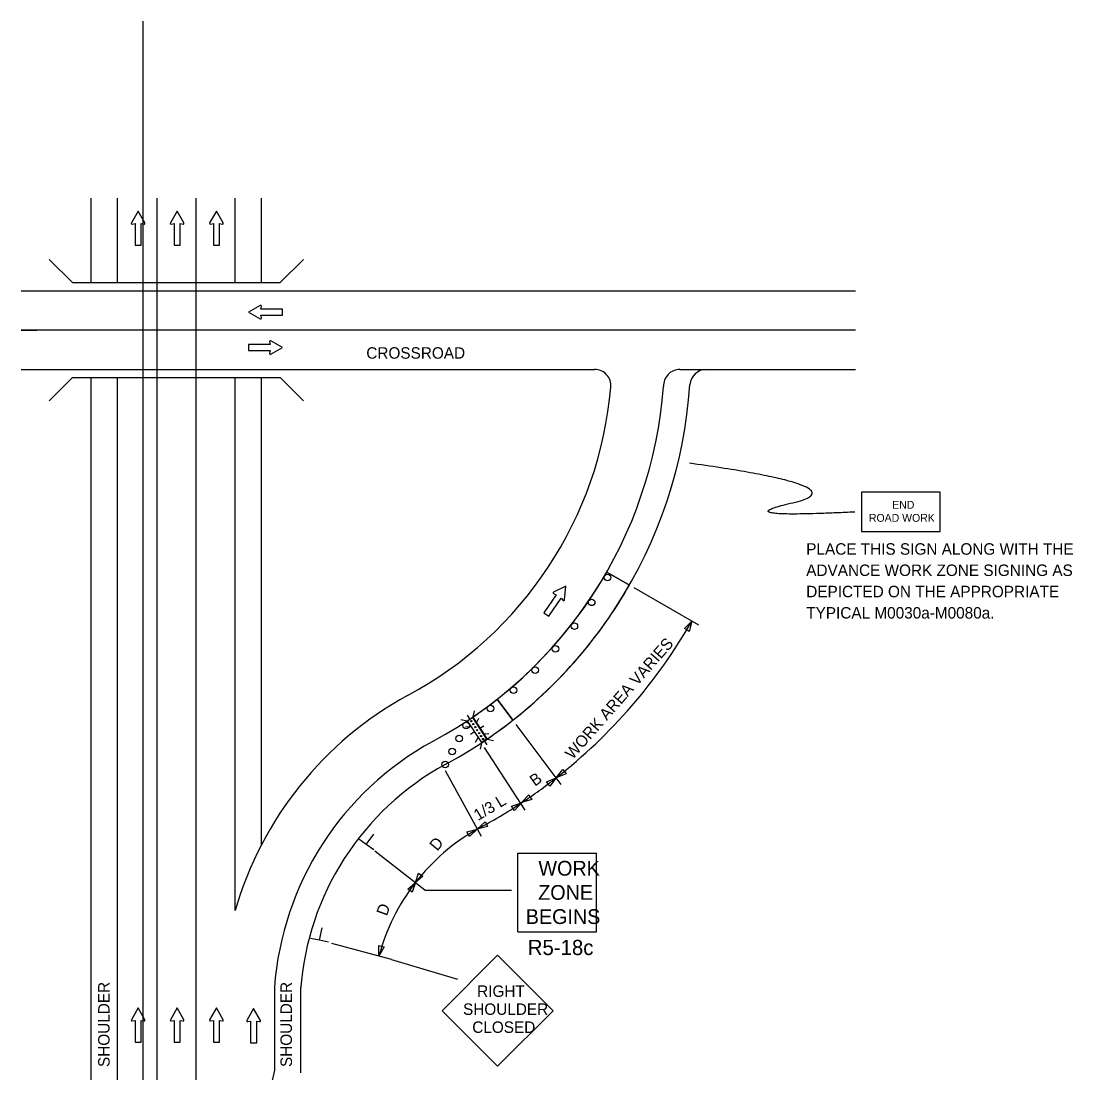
# Model space of a CAD drawing. Extents: x 16739 to 18471, y 6430 to 8295.
# Drawn here: x 16739 to 17381, y 7653 to 8295 of the extents above; entities that cross this region are included whole.
import ezdxf

# ---------------------------------------------------------------- set-up
doc = ezdxf.new("R2010")
doc.units = 0
for name, color, linetype in [('ALI_LEGAL_EX', 7, 'Continuous'), ('MT_SCRATCH_LEVEL_A', 7, 'Continuous'), ('MT_SCRATCH_LEVEL_E', 7, 'Continuous'), ('PAVT_EDGE_EX', 7, 'Continuous'), ('TRAFFIC_SIGNS_PR', 7, 'Continuous'), ('TYPICAL_TEXT_DIMEN_PR', 7, 'Continuous')]:
    doc.layers.add(name, color=color, linetype=linetype)

msp = doc.modelspace()

# ---------------------------------------------------------------- linework, layer by layer
at = {"layer": 'ALI_LEGAL_EX'}
for p, q in [((16813.1, 7643.13), (16813.1, 8295.46)), ((16821.4, 8187.24), (16821.4, 7232.8)), ((16845.4, 8187.24), (16845.4, 7232.8)), ((17248.19, 8106.7), (16738.55, 8106.7)), ((16893.33, 7654.82), (16893.33, 7654.82))]:
    msp.add_line(p, q, dxfattribs=at)
for points in [[(16821.4, 8187.24), (16821.4, 8162.24)], [(16845.4, 8187.24), (16845.4, 8162.24)], [(16738.55, 8106.7), (16748.19, 8106.7)], [(16738.55, 8106.7), (16748.19, 8106.7)], [(16848.19, 8106.7), (16823.19, 8106.7)], [(16948.19, 8106.7), (16923.19, 8106.7)], [(17048.19, 8106.7), (17023.19, 8106.7)], [(17148.19, 8106.7), (17123.19, 8106.7)], [(17248.19, 8106.7), (17223.19, 8106.7)], [(16821.4, 8077.7), (16821.4, 8062.24)], [(16845.4, 8077.7), (16845.4, 8062.24)], [(16821.4, 7987.24), (16821.4, 7962.24)], [(16845.4, 7987.24), (16845.4, 7962.24)], [(16821.4, 7887.24), (16821.4, 7862.24)], [(16845.4, 7887.24), (16845.4, 7862.24)], [(16821.4, 7787.24), (16821.4, 7762.24)], [(16845.4, 7787.24), (16845.4, 7762.24)], [(16821.4, 7687.24), (16821.4, 7662.24)], [(16845.4, 7687.24), (16845.4, 7662.24)]]:
    msp.add_lwpolyline(points, dxfattribs=at)
at = {"layer": 'MT_SCRATCH_LEVEL_A'}
for p, q in [((17096.28, 7958.99), (17110.14, 7951)), ((17110.14, 7951), (17096.28, 7958.99)), ((17038.98, 7868.53), (17029.37, 7881.32)), ((17029.37, 7881.32), (17038.98, 7868.53)), ((17038.98, 7868.53), (17029.37, 7881.32)), ((17038.98, 7868.53), (17029.37, 7881.32)), ((17014.38, 7870.33), (17014.43, 7870.41)), ((17014.46, 7870.37), (17023.18, 7856.95)), ((17014.46, 7870.37), (17023.17, 7856.95)), ((17014.46, 7870.37), (17023.17, 7856.95))]:
    msp.add_line(p, q, dxfattribs=at)
for radius, start, end in [(268.8, 308.26226, 330.24837), (284.8, 308.1875, 330.23752), (268.8, 304.31809, 308.26226), (268.8, 304.31809, 308.26226), (284.8, 304.24543, 308.18751), (284.8, 304.24543, 308.18751)]:
    msp.add_arc((16862.91, 8092.38), radius, start, end, dxfattribs=at)
at = {"layer": 'MT_SCRATCH_LEVEL_E'}
for p, q in [((16810.06, 8179.39), (16805.96, 8172.15)), ((16810.06, 8179.39), (16805.96, 8172.15)), ((16814.21, 8172.15), (16810.06, 8179.39)), ((16814.21, 8172.15), (16810.06, 8179.39)), ((16833.87, 8179.39), (16829.76, 8172.15)), ((16833.87, 8179.39), (16829.76, 8172.15)), ((16838.01, 8172.15), (16833.87, 8179.39)), ((16838.01, 8172.15), (16833.87, 8179.39)), ((16857.87, 8179.39), (16853.76, 8172.15)), ((16857.87, 8179.39), (16853.76, 8172.15)), ((16862.02, 8172.15), (16857.87, 8179.39)), ((16862.02, 8172.15), (16857.87, 8179.39)), ((16806.44, 8171.46), (16808.21, 8171.78)), ((16806.44, 8171.46), (16808.21, 8171.78)), ((16808.21, 8171.78), (16808.21, 8158.52)), ((16808.21, 8171.78), (16808.21, 8158.52)), ((16811.96, 8158.52), (16811.96, 8171.78)), ((16811.96, 8171.78), (16813.73, 8171.46)), ((16811.96, 8158.52), (16811.96, 8171.78)), ((16811.96, 8171.78), (16813.73, 8171.46)), ((16830.24, 8171.46), (16832.01, 8171.78)), ((16830.24, 8171.46), (16832.01, 8171.78)), ((16832.01, 8171.78), (16832.01, 8158.52)), ((16832.01, 8171.78), (16832.01, 8158.52)), ((16835.76, 8158.52), (16835.76, 8171.78)), ((16835.76, 8171.78), (16837.53, 8171.46)), ((16835.76, 8158.52), (16835.76, 8171.78)), ((16835.76, 8171.78), (16837.53, 8171.46)), ((16854.24, 8171.46), (16856.02, 8171.78)), ((16854.24, 8171.46), (16856.02, 8171.78)), ((16856.02, 8171.78), (16856.02, 8158.52)), ((16856.02, 8171.78), (16856.02, 8158.52)), ((16859.76, 8158.52), (16859.76, 8171.78)), ((16859.76, 8171.78), (16861.54, 8171.46)), ((16859.76, 8158.52), (16859.76, 8171.78)), ((16859.76, 8171.78), (16861.54, 8171.46)), ((16808.21, 8158.52), (16811.96, 8158.52)), ((16808.21, 8158.52), (16811.96, 8158.52)), ((16832.01, 8158.52), (16835.76, 8158.52)), ((16832.01, 8158.52), (16835.76, 8158.52)), ((16856.02, 8158.52), (16859.76, 8158.52)), ((16856.02, 8158.52), (16859.76, 8158.52)), ((16884.64, 8121.85), (16877.4, 8117.7)), ((16884.64, 8121.85), (16877.4, 8117.7)), ((16885.01, 8119.59), (16885.33, 8121.37)), ((16885.01, 8119.59), (16885.33, 8121.37)), ((16877.4, 8117.7), (16884.64, 8113.59)), ((16877.4, 8117.7), (16884.64, 8113.59)), ((16898.27, 8119.59), (16885.01, 8119.59)), ((16898.27, 8119.59), (16885.01, 8119.59)), ((16885.33, 8114.07), (16885.01, 8115.85)), ((16885.01, 8115.85), (16898.27, 8115.85)), ((16885.33, 8114.07), (16885.01, 8115.85)), ((16885.01, 8115.85), (16898.27, 8115.85)), ((16898.27, 8115.85), (16898.27, 8119.59)), ((16898.27, 8115.85), (16898.27, 8119.59)), ((16890.7, 8097.93), (16877.44, 8097.93)), ((16877.44, 8097.93), (16877.44, 8094.19)), ((16890.7, 8097.93), (16877.44, 8097.93)), ((16877.44, 8097.93), (16877.44, 8094.19)), ((16890.38, 8099.71), (16890.7, 8097.93)), ((16890.38, 8099.71), (16890.7, 8097.93)), ((16898.31, 8096.08), (16891.07, 8100.19)), ((16898.31, 8096.08), (16891.07, 8100.19)), ((16891.07, 8091.94), (16898.31, 8096.08)), ((16891.07, 8091.94), (16898.31, 8096.08)), ((16877.44, 8094.19), (16890.7, 8094.19)), ((16877.44, 8094.19), (16890.7, 8094.19)), ((16890.7, 8094.19), (16890.38, 8092.41)), ((16890.7, 8094.19), (16890.38, 8092.41)), ((17071.22, 7950.29), (17063.73, 7946.65)), ((17071.22, 7950.29), (17063.73, 7946.65)), ((17070.54, 7941.98), (17071.22, 7950.29)), ((17070.54, 7941.98), (17071.22, 7950.29)), ((17065.39, 7945.07), (17057.88, 7934.15)), ((17065.39, 7945.07), (17057.88, 7934.15)), ((17060.96, 7932.03), (17068.47, 7942.95)), ((17060.96, 7932.03), (17068.47, 7942.95)), ((17063.74, 7945.82), (17065.39, 7945.07)), ((17063.74, 7945.82), (17065.39, 7945.07)), ((17068.47, 7942.95), (17069.76, 7941.69)), ((17068.47, 7942.95), (17069.76, 7941.69)), ((17057.88, 7934.15), (17060.96, 7932.03)), ((17057.88, 7934.15), (17060.96, 7932.03)), ((16810.06, 7692.77), (16805.96, 7685.53)), ((16810.06, 7692.77), (16805.96, 7685.53)), ((16814.21, 7685.53), (16810.06, 7692.77)), ((16814.21, 7685.53), (16810.06, 7692.77)), ((16833.87, 7692.77), (16829.76, 7685.53)), ((16833.87, 7692.77), (16829.76, 7685.53)), ((16838.01, 7685.53), (16833.87, 7692.77)), ((16838.01, 7685.53), (16833.87, 7692.77)), ((16857.87, 7692.77), (16853.76, 7685.53)), ((16857.87, 7692.77), (16853.76, 7685.53)), ((16862.02, 7685.53), (16857.87, 7692.77)), ((16862.02, 7685.53), (16857.87, 7692.77)), ((16880.62, 7692.43), (16876.51, 7685.19)), ((16880.62, 7692.43), (16876.51, 7685.19)), ((16884.76, 7685.19), (16880.62, 7692.43)), ((16884.76, 7685.19), (16880.62, 7692.43)), ((16806.44, 7684.84), (16808.21, 7685.16)), ((16806.44, 7684.84), (16808.21, 7685.16)), ((16808.21, 7685.16), (16808.21, 7671.9)), ((16808.21, 7685.16), (16808.21, 7671.9)), ((16811.96, 7671.9), (16811.96, 7685.16)), ((16811.96, 7685.16), (16813.73, 7684.84)), ((16811.96, 7671.9), (16811.96, 7685.16)), ((16811.96, 7685.16), (16813.73, 7684.84)), ((16830.24, 7684.84), (16832.01, 7685.16)), ((16830.24, 7684.84), (16832.01, 7685.16)), ((16832.01, 7685.16), (16832.01, 7671.9)), ((16832.01, 7685.16), (16832.01, 7671.9)), ((16835.76, 7671.9), (16835.76, 7685.16)), ((16835.76, 7685.16), (16837.53, 7684.84)), ((16835.76, 7671.9), (16835.76, 7685.16)), ((16835.76, 7685.16), (16837.53, 7684.84)), ((16854.24, 7684.84), (16856.02, 7685.16)), ((16854.24, 7684.84), (16856.02, 7685.16)), ((16856.02, 7685.16), (16856.02, 7671.9)), ((16856.02, 7685.16), (16856.02, 7671.9)), ((16859.76, 7671.9), (16859.76, 7685.16)), ((16859.76, 7685.16), (16861.54, 7684.84)), ((16859.76, 7671.9), (16859.76, 7685.16)), ((16859.76, 7685.16), (16861.54, 7684.84)), ((16876.99, 7684.5), (16878.77, 7684.82)), ((16876.99, 7684.5), (16878.77, 7684.82)), ((16878.77, 7684.82), (16878.77, 7671.56)), ((16878.77, 7684.82), (16878.77, 7671.56)), ((16882.51, 7671.56), (16882.51, 7684.82)), ((16882.51, 7684.82), (16884.28, 7684.5)), ((16882.51, 7671.56), (16882.51, 7684.82)), ((16882.51, 7684.82), (16884.28, 7684.5)), ((16808.21, 7671.9), (16811.96, 7671.9)), ((16808.21, 7671.9), (16811.96, 7671.9)), ((16832.01, 7671.9), (16835.76, 7671.9)), ((16832.01, 7671.9), (16835.76, 7671.9)), ((16856.02, 7671.9), (16859.76, 7671.9)), ((16856.02, 7671.9), (16859.76, 7671.9)), ((16878.77, 7671.56), (16882.51, 7671.56)), ((16878.77, 7671.56), (16882.51, 7671.56))]:
    msp.add_line(p, q, dxfattribs=at)
for centre, start, end in [((16806.36, 8171.92), 150.42484, 279.96381), ((16806.36, 8171.92), 150.42484, 279.96381), ((16813.8, 8171.92), 260.03619, 29.77312), ((16813.8, 8171.92), 260.03619, 29.77312), ((16830.16, 8171.92), 150.42484, 279.96381), ((16830.16, 8171.92), 150.42484, 279.96381), ((16837.6, 8171.92), 260.03619, 29.77312), ((16837.6, 8171.92), 260.03619, 29.77312), ((16854.17, 8171.92), 150.42484, 279.96381), ((16854.17, 8171.92), 150.42484, 279.96381), ((16861.61, 8171.92), 260.03619, 29.77312), ((16861.61, 8171.92), 260.03619, 29.77312), ((16884.87, 8121.44), 350.03619, 119.77312), ((16884.87, 8121.44), 350.03619, 119.77312), ((16884.87, 8114), 240.42484, 9.96381), ((16884.87, 8114), 240.42484, 9.96381), ((16890.84, 8099.78), 60.42484, 189.96381), ((16890.84, 8099.78), 60.42484, 189.96381), ((16890.84, 8092.34), 170.03619, 299.77312), ((16890.84, 8092.34), 170.03619, 299.77312), ((17063.94, 7946.24), 115.92484, 245.46381), ((17063.94, 7946.24), 115.92484, 245.46381), ((17070.07, 7942.02), 225.53619, 355.27312), ((17070.07, 7942.02), 225.53619, 355.27312), ((16806.36, 7685.3), 150.42484, 279.96381), ((16806.36, 7685.3), 150.42484, 279.96381), ((16813.8, 7685.3), 260.03619, 29.77312), ((16813.8, 7685.3), 260.03619, 29.77312), ((16830.16, 7685.3), 150.42484, 279.96381), ((16830.16, 7685.3), 150.42484, 279.96381), ((16837.6, 7685.3), 260.03619, 29.77312), ((16837.6, 7685.3), 260.03619, 29.77312), ((16854.17, 7685.3), 150.42484, 279.96381), ((16854.17, 7685.3), 150.42484, 279.96381), ((16861.61, 7685.3), 260.03619, 29.77312), ((16861.61, 7685.3), 260.03619, 29.77312), ((16876.91, 7684.96), 150.42484, 279.96381), ((16876.91, 7684.96), 150.42484, 279.96381), ((16884.36, 7684.96), 260.03619, 29.77312), ((16884.36, 7684.96), 260.03619, 29.77312)]:
    msp.add_arc(centre, 0.463, start, end, dxfattribs=at)
at = {"layer": 'PAVT_EDGE_EX'}
for p, q in [((16781.4, 8135.7), (16781.4, 8187.24)), ((16797.4, 8135.7), (16797.4, 8187.24)), ((16869.4, 8135.7), (16869.4, 8187.24)), ((16885.4, 8135.7), (16885.4, 8187.24)), ((16769.9, 8135.7), (16755.76, 8149.85)), ((16896.9, 8135.7), (16911.04, 8149.85)), ((16769.9, 8135.7), (16896.9, 8135.7)), ((16738.55, 8130.7), (17248.19, 8130.7)), ((16738.55, 8082.7), (17088.86, 8082.7)), ((17141.02, 8082.7), (17248.19, 8082.7)), ((16755.76, 8063.56), (16769.9, 8077.7)), ((16769.9, 8077.7), (16896.9, 8077.7)), ((16781.4, 7232.8), (16781.4, 8077.7)), ((16797.4, 7232.8), (16797.4, 8077.7)), ((16869.4, 7752.28), (16869.4, 8077.7)), ((16885.4, 7792.38), (16885.4, 8077.7)), ((16911.04, 8063.56), (16896.9, 8077.7)), ((16893.33, 7705.31), (16893.33, 7654.82)), ((16909.29, 7705.31), (16909.29, 7653.2)), ((16893.33, 7654.82), (16869.4, 7545.32))]:
    msp.add_line(p, q, dxfattribs=at)
for centre, radius, start, end in [((17088.86, 8072.7), 10, 355.02362, 90), ((17141.02, 8072.7), 10.03, 90, 182.45519), ((17157.05, 8072.7), 10, 90, 176.17344), ((16862.91, 8092.38), 236.8, 298.14539, 355.02362), ((16862.91, 8092.38), 268.8, 298.20808, 355.71052), ((16862.91, 8092.38), 284.8, 298.23413, 356.17344), ((17079.55, 7691.68), 218.71, 118.67196, 163.91539), ((17079.55, 7691.68), 186.71, 118.67196, 175.81301), ((17079.55, 7691.68), 170.71, 118.67196, 175.81301)]:
    msp.add_arc(centre, radius, start, end, dxfattribs=at)
at = {"layer": 'TRAFFIC_SIGNS_PR'}
for p, q in [((17012.72, 7869.3), (17011.19, 7871.66)), ((17015.26, 7874.31), (17014.43, 7870.41)), ((17007.12, 7869.02), (17011.02, 7868.19)), ((17010.08, 7864.46), (17013.33, 7864.63)), ((17013.62, 7867.93), (17013.62, 7867.93)), ((17014.8, 7866.1), (17014.8, 7866.1)), ((17015.99, 7864.28), (17015.99, 7864.28)), ((17016.76, 7866.83), (17018.23, 7869.73)), ((17018.83, 7863.63), (17021.2, 7865.16)), ((17015.43, 7861.41), (17013.06, 7859.88)), ((17016.22, 7855.02), (17017.69, 7857.92)), ((17017.17, 7862.46), (17017.17, 7862.46)), ((17018.36, 7860.64), (17018.36, 7860.64)), ((17019.54, 7858.81), (17019.54, 7858.81)), ((17021.09, 7860.16), (17024.34, 7860.33)), ((17019.83, 7854.63), (17019.01, 7850.73)), ((17020.73, 7856.99), (17020.73, 7856.99)), ((17021.54, 7855.74), (17023.08, 7853.38)), ((17023.24, 7856.85), (17027.15, 7856.02)), ((17042.06, 7739.38), (17042.06, 7787.38)), ((17042.06, 7787.38), (17090.06, 7787.38)), ((17090.06, 7739.38), (17090.06, 7787.38)), ((17042.06, 7739.38), (17090.06, 7739.38)), ((17029.66, 7725.06), (16995.72, 7691.12)), ((17063.6, 7691.12), (17029.66, 7725.06)), ((16995.72, 7691.12), (17029.66, 7657.18)), ((17029.66, 7657.18), (17063.6, 7691.12))]:
    msp.add_line(p, q, dxfattribs=at)
for points in [[(17251.92, 7983.75), (17299.92, 7983.75), (17299.92, 8007.75), (17251.92, 8007.75)], [(17019.9, 7854.95), (17011.34, 7868.12), (17014.36, 7870.09), (17022.92, 7856.92)]]:
    msp.add_lwpolyline(points, close=True, dxfattribs=at)
for centre, radius in [((17096.69, 7955.69), 2), ((17087.09, 7940.47), 2), ((17076.51, 7925.91), 2), ((17064.98, 7912.09), 2), ((17052.56, 7899.07), 2), ((17039.3, 7886.9), 2), ((17025.26, 7875.64), 2), ((17010.4, 7865.26), 2), ((17013.63, 7867.91), 0.379), ((17014.8, 7866.1), 0.379), ((17015.99, 7864.28), 0.379), ((17006.15, 7857.33), 2), ((17017.17, 7862.46), 0.379), ((17018.36, 7860.64), 0.379), ((17019.54, 7858.81), 0.379), ((17001.89, 7849.39), 2), ((17020.73, 7856.99), 0.379), ((16997.64, 7841.46), 2)]:
    msp.add_circle(centre, radius, dxfattribs=at)
msp.add_open_spline([(17247.72, 7995.64), (17167.03, 7991.52), (17252.05, 8010.87), (17146.91, 8025.43)], degree=2, dxfattribs=at)
at = {"layer": 'TYPICAL_TEXT_DIMEN_PR'}
for p, q in [((17152.6, 7926.54), (17113.01, 7949.35)), ((17143.69, 7924.44), (17148.26, 7929.03)), ((17148.26, 7929.03), (17146.59, 7922.77)), ((17145.14, 7923.61), (17143.69, 7924.44)), ((17146.59, 7922.77), (17145.14, 7923.61)), ((17068.46, 7829.3), (17040.97, 7865.88)), ((17046.46, 7813.57), (17021.55, 7851.88)), ((17065.42, 7833.35), (17069.41, 7838.44)), ((17069.41, 7838.44), (17070.42, 7837.1)), ((16997.69, 7837.71), (17019.61, 7797.63)), ((17059.42, 7830.93), (17065.42, 7833.35)), ((17065.42, 7833.35), (17061.43, 7828.25)), ((17071.43, 7835.76), (17065.42, 7833.35)), ((17070.42, 7837.1), (17071.43, 7835.76)), ((17060.42, 7829.59), (17059.42, 7830.93)), ((17061.43, 7828.25), (17060.42, 7829.59)), ((17044.32, 7818.16), (17048.65, 7822.97)), ((17050.48, 7820.16), (17044.32, 7818.16)), ((17048.65, 7822.97), (17049.57, 7821.57)), ((17049.57, 7821.57), (17050.48, 7820.16)), ((17038.09, 7816.1), (17044.24, 7818.1)), ((17039, 7814.69), (17038.09, 7816.1)), ((17039.91, 7813.29), (17039, 7814.69)), ((17044.24, 7818.1), (17039.91, 7813.29)), ((17017.24, 7802.05), (17021.96, 7806.48)), ((17021.96, 7806.48), (17022.75, 7805)), ((17010.86, 7800.44), (17017.15, 7801.97)), ((17011.67, 7798.97), (17010.86, 7800.44)), ((17017.15, 7801.97), (17012.47, 7797.5)), ((17023.54, 7803.52), (17017.24, 7802.05)), ((17022.75, 7805), (17023.54, 7803.52)), ((16949.4, 7792.62), (16944.86, 7795.94)), ((16949.4, 7792.62), (16953.99, 7798.92)), ((17012.47, 7797.5), (17011.67, 7798.97)), ((16953.95, 7789.31), (16949.4, 7792.62)), ((16985.25, 7764.78), (16954.73, 7788.44)), ((16979.41, 7769.32), (16981.38, 7775.06)), ((16981.38, 7775.06), (16982.68, 7774.18)), ((16982.68, 7774.18), (16983.98, 7773.31)), ((16974.82, 7765.33), (16979.4, 7769.31)), ((16979.4, 7769.31), (16977.43, 7763.57)), ((16983.98, 7773.31), (16979.41, 7769.32)), ((16976.13, 7764.45), (16974.82, 7765.33)), ((16977.43, 7763.57), (16976.13, 7764.45)), ((16985.25, 7764.78), (17038.11, 7764.78)), ((16920.92, 7734.14), (16922.53, 7741.76)), ((16920.92, 7734.14), (16915.42, 7735.3)), ((16926.43, 7732.98), (16920.92, 7734.14)), ((16964.81, 7722.45), (16928.31, 7732.24)), ((16957.16, 7724.5), (16957.13, 7730.98)), ((16957.13, 7730.98), (16958.75, 7730.55)), ((16960.37, 7730.12), (16957.16, 7724.5)), ((16958.75, 7730.55), (16960.37, 7730.12)), ((16964.81, 7722.45), (17005.16, 7710.35))]:
    msp.add_line(p, q, dxfattribs=at)
for centre, radius, start, end in [((16862.91, 8092.38), 328.8, 308.01895, 330.21055), ((16862.91, 8092.38), 328.8, 303.48747, 308.01895), ((16862.91, 8092.38), 328.8, 297.99394, 303.47034), ((17079.55, 7691.68), 126.71, 119.4981, 142.21718), ((17079.55, 7691.68), 126.71, 142.21336, 164.98774)]:
    msp.add_arc(centre, radius, start, end, dxfattribs=at)

# ---------------------------------------------------------------- texts
at = {"layer": 'TRAFFIC_SIGNS_PR'}
for s, height, p in [('END', 4.789, (17270.67, 7997.66)), ('ROAD WORK', 4.789, (17256.43, 7989.68)), ('PLACE THIS SIGN ALONG WITH THE', 7, (17218.14, 7969.58)), ('ADVANCE WORK ZONE SIGNING AS', 7, (17218.14, 7956.58)), ('DEPICTED ON THE APPROPRIATE', 7, (17218.14, 7943.58)), ('TYPICAL M0030a-M0080a.', 7, (17218.14, 7930.58)), ('WORK', 9.021, (17054.56, 7773.59)), ('ZONE', 9.021, (17054.41, 7758.83)), ('BEGINS', 9.021, (17046.82, 7744.07)), ('R5-18c', 9.3, (17048.07, 7725.09)), ('RIGHT', 7, (17017.13, 7699.57)), ('SHOULDER', 7, (17008.51, 7688.57)), ('CLOSED', 7, (17014.15, 7677.57))]:
    msp.add_text(s, height=height, dxfattribs=at).set_placement(p)
at = {"layer": 'TYPICAL_TEXT_DIMEN_PR'}
for s, rotation, p in [('CROSSROAD', 0, (16949.44, 8089.27)), ('WORK AREA VARIES', 48.75806, (17075.45, 7844.16)), ('B', 35.7516, (17052.41, 7827.84)), ('1/3 L', 30.81724, (17017.65, 7806.89)), ('D', 50.66136, (16992.78, 7788.23)), ('D', 70.50196, (16961.99, 7748.6)), ('SHOULDER', 90.06426, (16792.66, 7656.72)), ('SHOULDER', 90.06426, (16904.03, 7656.72))]:
    msp.add_text(s, height=7, rotation=rotation, dxfattribs=at).set_placement(p)

doc.saveas('drawing.dxf')
